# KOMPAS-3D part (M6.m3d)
File: created 17.03.2016 12:24:08, last saved 18.09.2016 14:37:21.
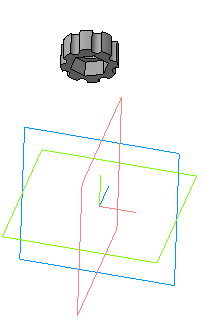
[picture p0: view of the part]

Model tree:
1. Эскиз:1
2. Операция выдавливания:1
     Расстояние 1 = 12
3. Эскиз:2
4. Вырезать элемент выдавливания:1
     Расстояние 1 = 20
5. Эскиз:3
6. Вырезать элемент выдавливания:2
     Расстояние 1 = 10
7. Скругление:1
     Радиус = 7
8. Скругление:2
     Радиус = 7
9. Скругление:3
     Радиус = 13
10. Эскиз:4
11. Вырезать элемент выдавливания:3
     Расстояние 1 = 20
12. Эскиз:5
13. Операция выдавливания:2
     Расстояние 1 = 1.5
14. Эскиз:6
15. Операция выдавливания:3
     Расстояние 1 = 1.5; Расстояние 2 = 12
16. Эскиз:7
17. Вырезать элемент выдавливания:4
     Расстояние 1 = 20
18. Эскиз:8
19. Вырезать элемент выдавливания:5
     Расстояние 2 = 30; Расстояние 1 = 30
20. Масштабирование:2
     Коэффициент = 1.06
